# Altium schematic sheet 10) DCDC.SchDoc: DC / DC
size A3; Origin: Eagle; DocumentNumber: 10; SheetNumber: 10; SheetTotal: 10
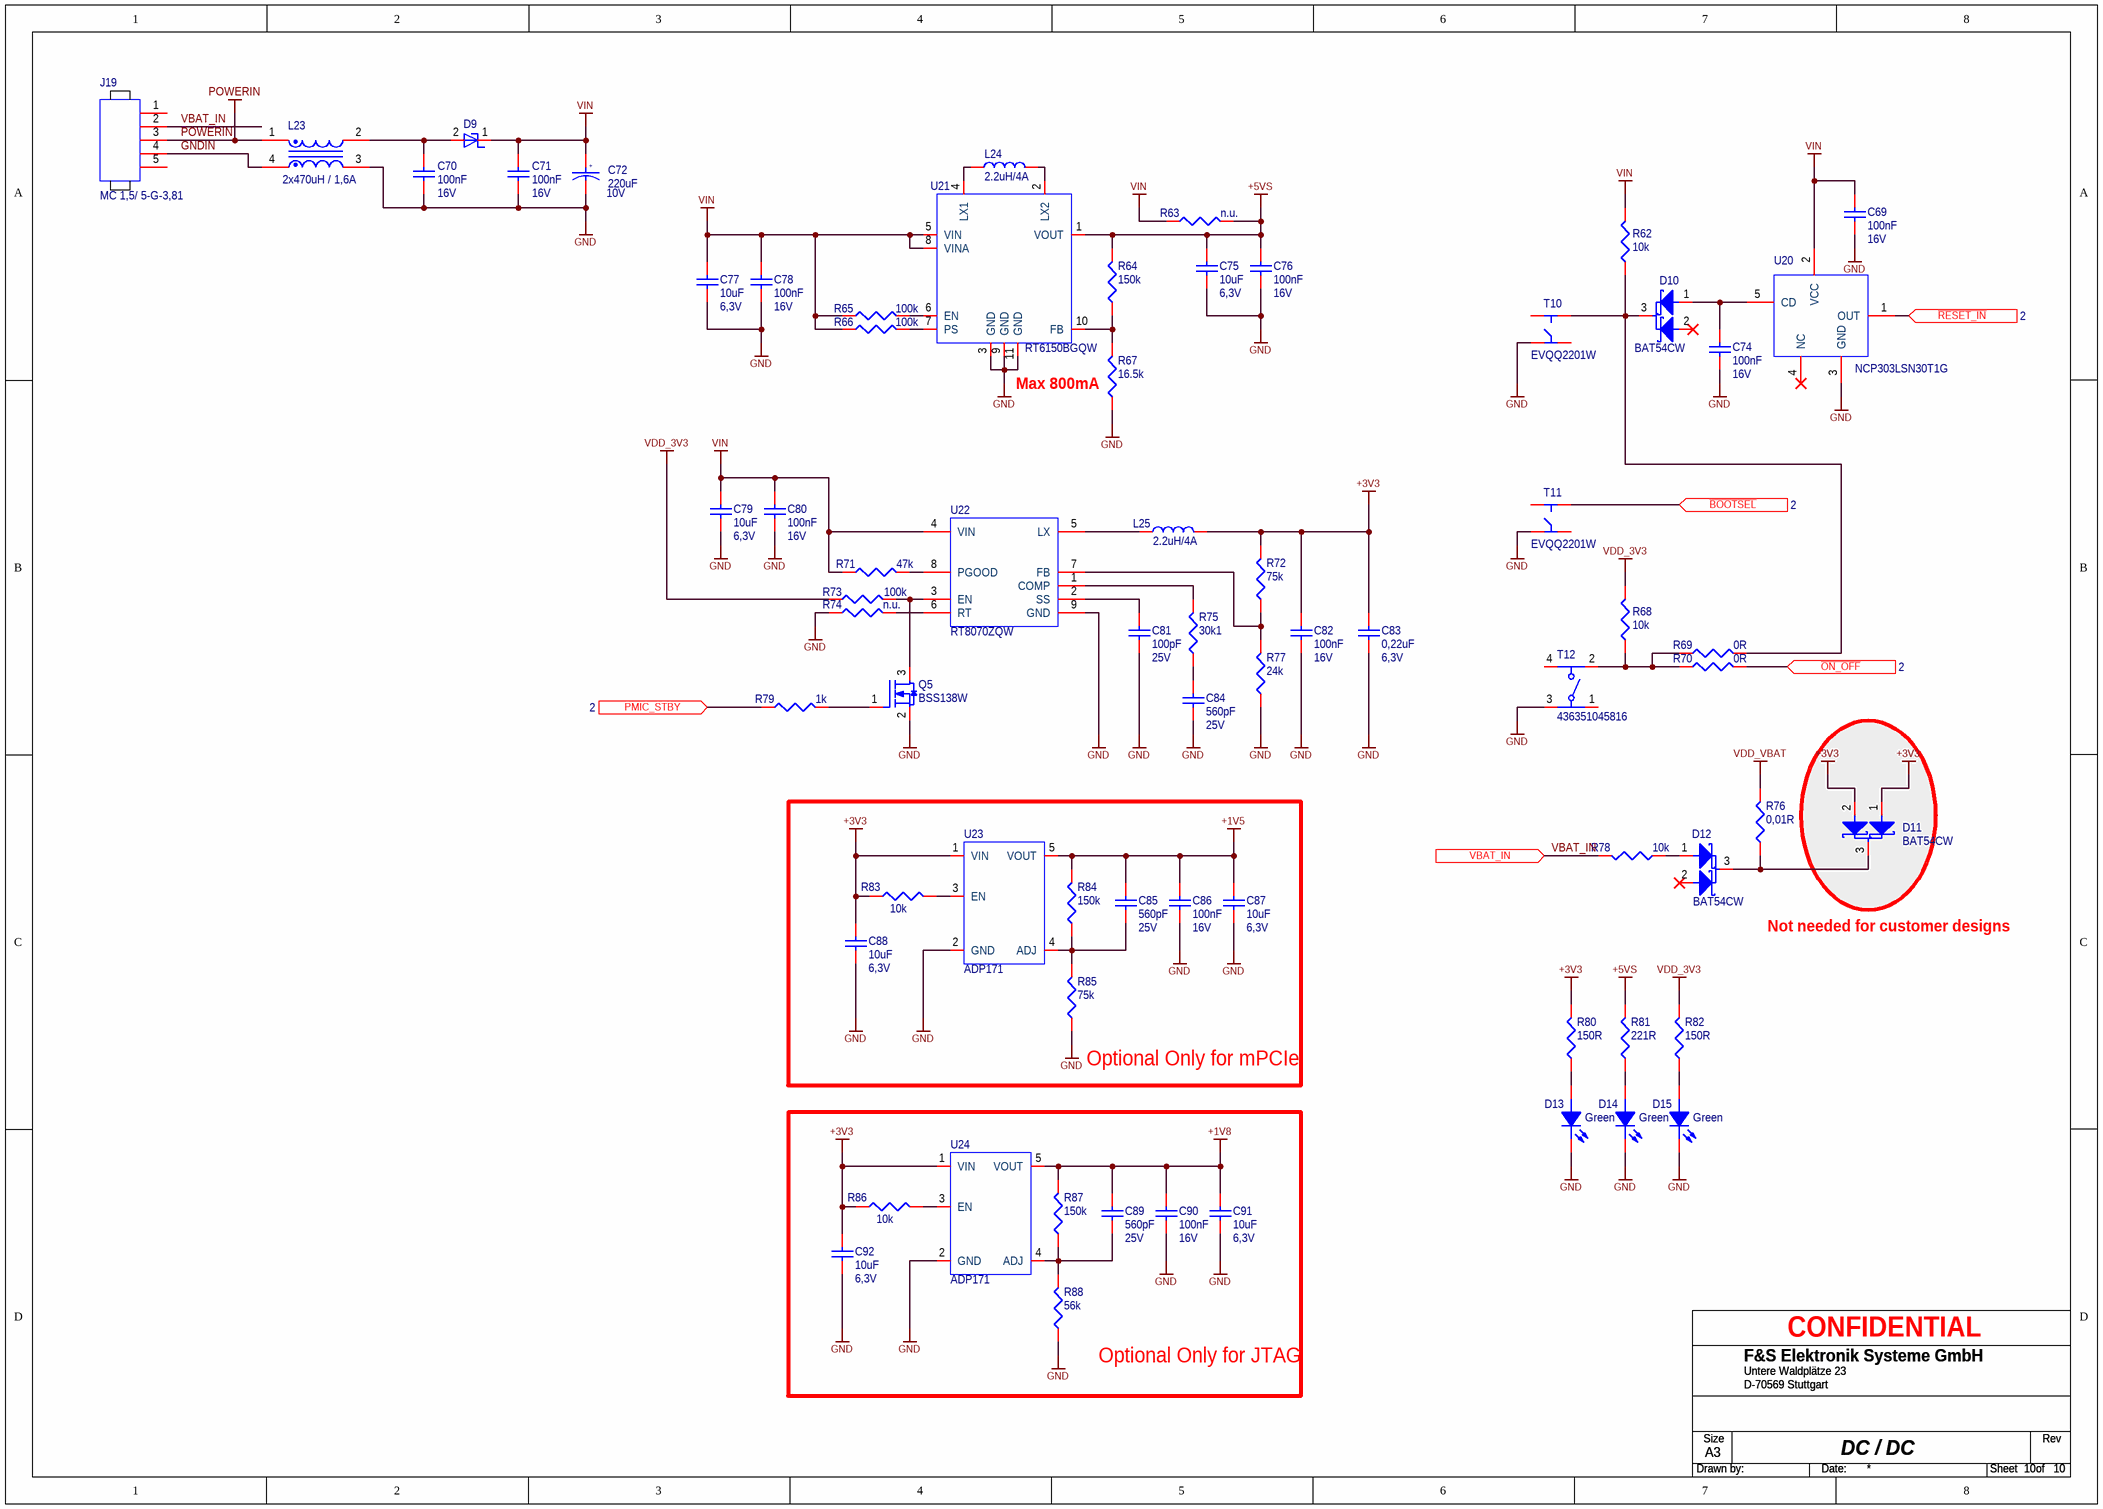
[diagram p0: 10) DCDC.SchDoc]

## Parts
C69  100nF  Voltage: 16V  [C0402]
C70  100nF  Voltage: 16V  [C0402]
C71  100nF  Voltage: 16V  [C0402]
C72  220uF  Voltage: 10V  [C_2312]
C74  100nF  Voltage: 16V  [C0402]
C75  10uF  Voltage: 6,3V  [C0603]
C76  100nF  Voltage: 16V  [C0402]
C77  10uF  Voltage: 6,3V  [C0603]
C78  100nF  Voltage: 16V  [C0402]
C79  10uF  Voltage: 6,3V  [C0603]
C80  100nF  Voltage: 16V  [C0402]
C81  100pF  Voltage: 25V  [C0402]
C82  100nF  Voltage: 16V  [C0402]
C83  0,22uF  Voltage: 6,3V  [C0805]
C84  560pF  Voltage: 25V  [C0402]
C85  560pF  Voltage: 25V  [C0402]
C86  100nF  Voltage: 16V  [C0402]
C87  10uF  Voltage: 6,3V  [C0603]
C88  10uF  Voltage: 6,3V  [C0603]
C89  560pF  Voltage: 25V  [C0402]
C90  100nF  Voltage: 16V  [C0402]
C91  10uF  Voltage: 6,3V  [C0603]
C92  10uF  Voltage: 6,3V  [C0603]
D9  SK56L  [DO-214AB]  (value not drawn)
D10  BAT54CW  [SOT323 (SC70)]
D11  BAT54CW  [SOT323 (SC70)]
D12  BAT54CW  [SOT323 (SC70)]
D13  Green  [LED0603]
D14  Green  [LED0603]
D15  Green  [LED0603]
J19  MC 1,5/ 5-G-3,81  [691322310005]
L23  2x470uH / 1,6A  [WE-SL5]
L24  2.2uH/4A  [LD-5X5M-VLC5045]
L25  2.2uH/4A  [LD-5X5M-VLC5045]
Q5  BSS138W  [SOT323 (SC70)]
R62  10k  [R0402]
R63  n.u.  [R0805]
R64  150k  [R0402]
R65  100k  [R0402]
R66  100k  [R0402]
R67  16.5k  [R0402]
R68  10k  [R0402]
R69  0R  [R0402]
R70  0R  [R0402]
R71  47k  [R0402]
R72  75k  [R0402]
R73  100k  [R0402]
R74  n.u.  [R0402]
R75  30k1  [R0402]
R76  0,01R  [R0805]
R77  24k  [R0402]
R78  10k  [R0402]
R79  1k  [R0402]
R80  150R  [R0402]
R81  221R  [R0402]
R82  150R  [R0402]
R83  10k  [R0402]
R84  150k  [R0402]
R85  75k  [R0402]
R86  10k  [R0402]
R87  150k  [R0402]
R88  56k  [R0402]
T10  EVQQ2201W  [EVQQ2 Switch]
T11  EVQQ2201W  [EVQQ2 Switch]
T12  436351045816  [436351045816]
U20  NCP303LSN30T1G  [SOT23-5]
U21  RT6150BGQW  [SON50P250X80_HS-11N]
U22  RT8070ZQW  [WDFN8_0.65P_300X80]
U23  ADP171  [SOT23-5]
U24  ADP171  [SOT23-5]

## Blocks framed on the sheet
Optional Only for mPCIe: C85-C88 R83-R85 U23
Optional Only for JTAG: C89-C92 R86-R88 U24

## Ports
PMIC_STBY (in, see 2), VBAT_IN (in), ~{BOOTSEL} (in, see 2), ~{ON_OFF} (in, see 2), ~{RESET_IN} (in, see 2)

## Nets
+1V5: C85.2 C86.2 C87.2 R84.2 U23.5(VOUT)
+1V8: C89.2 C90.2 C91.2 R87.2 U24.5(VOUT)
+3V3: C82.2 C83.2 C88.2 C92.2 D11.1(ANODE1) D11.2(ANODE2) L25.2 R72.2 R80.2 R83.1 R86.1 U23.1(VIN) U24.1(VIN)
+5VS: C75.2 C76.2 R63.2 R64.2 R81.2 U21.1(VOUT)
GND: C69.1 C70.1 C71.1 C72.2 C74.1 C75.1 C76.1 C77.1 C78.1 C79.1 C80.1 C81.1 C82.1 C83.1 C84.1 C86.1 C87.1 C88.1 C90.1 C91.1 C92.1 D13.1(CAT_GRN) D14.1(CAT_GRN) D15.1(CAT_GRN) L23.3 Q5.2 R67.1 R74.1 R77.1 R85.1 R88.1 T10.3 T11.3 T12.3 U20.3(GND) U21.3(GND) U21.9(GND) U21.11(GND) U22.9(GND) U23.2(GND) U24.2(GND)
POWERIN: J19.3 L23.1
VDD_3V3: R68.2 R73.1 R82.2
VDD_VBAT: R76.2
VIN: C69.2 C71.2 C72.1 C77.2 C78.2 C79.2 C80.2 D9.1(Anode) R62.2 R63.1 R65.1 R66.1 R71.1 U20.2(VCC) U21.5(VIN) U21.8(VINA) U22.4(VIN)
~{BOOTSEL}: T11.2 ; port ~{BOOTSEL}
GNDIN: J19.4 L23.4
~{ON_OFF}: R70.2 ; port ~{ON_OFF}
PMIC_STBY: R79.1 ; port PMIC_STBY
~{RESET_IN}: U20.1(OUT) ; port ~{RESET_IN}
VBAT_IN: J19.2 R78.2 ; port VBAT_IN
NetC70_2: C70.2 D9.2(Cathode) L23.2
NetC74_2: C74.2 D10.1(ANODE1) U20.5(CD)
NetC81_2: C81.2 U22.2(SS)
NetC84_2: C84.2 R75.1
NetC85_1: C85.1 R84.1 R85.2 U23.4(ADJ)
NetC89_1: C89.1 R87.1 R88.2 U24.4(ADJ)
NetD10_3: D10.3(CATHODE) R62.1 R69.2 T10.2
NetD11_3: D11.3(CATHODE) D12.3(CATHODE) R76.1
NetD12_1: D12.1(ANODE1) R78.1
NetD13_2: D13.2(AN_GRN) R80.1
NetD14_2: D14.2(AN_GRN) R81.1
NetD15_2: D15.2(AN_GRN) R82.1
NetL24_1: L24.1 U21.4(LX1)
NetL24_2: L24.2 U21.2(LX2)
NetL25_1: L25.1 U22.5(LX)
NetQ5_1: Q5.1 R79.2
NetQ5_3: Q5.3 R73.2 U22.3(EN)
NetR64_1: R64.1 R67.2 U21.10(FB)
NetR65_2: R65.2 U21.6(EN)
NetR66_2: R66.2 U21.7(PS)
NetR68_1: R68.1 R69.1 R70.1 T12.2
NetR71_2: R71.2 U22.8(PGOOD)
NetR72_1: R72.1 R77.2 U22.7(FB)
NetR74_2: R74.2 U22.6(RT)
NetR75_2: R75.2 U22.1(COMP)
NetR83_2: R83.2 U23.3(EN)
NetR86_2: R86.2 U24.3(EN)

Not connected (* = marked no-connect by the designer): D10 2(ANODE2)*; D12 2(ANODE2)*; J19 1 5; T10 1 4; T11 1 4; T12 1 4; U20 4(NC)*

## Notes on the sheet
- (near R67) Max 800mA
- Not needed for customer designs

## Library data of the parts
C69-C71 C74 C76 C78 C80 C82 C86 C90 = 380: 100nF  10%  16V  X7R  0402; FS-EDV-Nummer: B.CKV.42; Class: Capacitor Ceramic; Tolerance: 10; ID: 380
C72 = 718: 220uF  20%  10V  2312  Typ: C; FS-EDV-Nummer: B.CTA.16; Class: Capacitor Tantal; Tolerance: 20; ID: 718
C75 C77 C79 C87 C88 C91 C92 = 406: 10uF  20%  6,3V  X5R  0603; FS-EDV-Nummer: B.CKV.46; Class: Capacitor Ceramic; Tolerance: 20; ID: 406
C81 = 387: 100pF  5%  25V  C0G/NP0  0402; FS-EDV-Nummer: B.CKV.68; Class: Capacitor Ceramic; Tolerance: 5; ID: 387
C83 = 439: 0,22uF  10%  6,3V  X7R  0805; FS-EDV-Nummer: B.CKV.62; Class: Capacitor Ceramic; Tolerance: 10; ID: 439
C84 C85 C89 = 388: 560pF  5%  25V  X7R  0402; FS-EDV-Nummer: B.CKV.71; Class: Capacitor Ceramic; Tolerance: 5; ID: 388
D9 = 2696: SK56L-TP  60V  5A  Common Anode  DO-214AB; ID: 2696; Class: DIOD; FS-EDV-Nummer: B.DSCHOT.4
D10-D12 = 2695: BAT54CW  30V  200mA  Dual Common Cathode SOT-323; FS-EDV-Nummer: B.DSCHOT.5; Class: DIOD; ID: 2695
D13-D15 = 2744: LED  Green  View 120°  0603; Part Number: APT1608CGCK; ID: 2744; FS-EDV-Nummer: B.DLED.11
J19 = 2729: Stiftl. 5 pol.1 reih. R3,81  liegend; ID: 2729; Class: Connector; FS-EDV-Nummer: B.MST.1R5PS.5
L23 = 2697: 2x470uH 1,6A SMD; ID: 2697; FS-EDV-Nummer: B.L.56; Power: 1,6A
L24 L25 = 2741: ID: 2741; FS-EDV-Nummer: B.L.42; Power: 4A
Q5 = 2689: BSS138W SOT323(SC-70) N-Kanal; FS-EDV-Nummer: B.TPMFN.10; Class: MOSFET; ID: 2689
R62 R68 R78 R83 R86 = 170: 10k 1/16W 1% SMD 0402; FS-EDV-Nummer: B.R10K.3; Tolerance: 1; ID: 170
R63 = B.R000.2.S: 0R00 0,125W max 5% SMD 0805; Power: 0,125W; Tolerance: 5; ID: 6
R64 R84 R87 = 204: 150k 1/16W 1% SMD 0402; FS-EDV-Nummer: B.R150K.2; Tolerance: 1; ID: 204
R65 R66 R73 = 177: 100k 1/16W 1% SMD 0402; FS-EDV-Nummer: B.R100K.3; Tolerance: 1; ID: 177
R67 = 303: 16.5k 1/16W 1% SMD 0402; FS-EDV-Nummer: B.R16K5.1; Tolerance: 1; ID: 303
R69 R70 = 173: 0R 1/16W max 5% SMD 0402; FS-EDV-Nummer: B.R0R0.1; Tolerance: 5; ID: 173
R71 = 186: 47k 1/16W 1% SMD 0402; FS-EDV-Nummer: B.R47K0.1; Tolerance: 1; ID: 186
R72 R85 = 191: 75k 1/16W 1% SMD 0402; FS-EDV-Nummer: B.R75K0.1; Tolerance: 1; ID: 191
R74 = Resistor
R75 = 197: 30k1 1/16W 1% SMD 0402; FS-EDV-Nummer: B.R30K1.1; Tolerance: 1; ID: 197
R76 = 187: 0,01R 1/4W max 5% SMD 0805; FS-EDV-Nummer: B.R0R01.1; Tolerance: 5; ID: 187
R77 = 254: 24k 1/16W 1% SMD 0402; FS-EDV-Nummer: B.R24k0.1; Tolerance: 1; ID: 254
R79 = 166: 1k 1/16W 1% SMD 0402; FS-EDV-Nummer: B.R1K00.1; Tolerance: 1; ID: 166
R80 R82 = 172: 150R 1/16W 1% SMD 0402; FS-EDV-Nummer: B.R150R.1; Tolerance: 1; ID: 172
R81 = 174: 221R 1/16W 1% SMD 0402; FS-EDV-Nummer: B.R221R.1; Tolerance: 1; ID: 174
R88 = 326: 56k 1/16W 1% SMD 0402; FS-EDV-Nummer: B.R56K.2; Tolerance: 1; ID: 326
T10 T11 = 2735: Miniatur-Tastschalter Serie EVQ SMD; FS-EDV-Nummer: B.MSW.4; Voltage: 15V; Class: Switch; Power: 20 mA; ID: 2735
T12 = 2736: Tact Switch side push; FS-EDV-Nummer: B.MSW.5; Voltage: 12V; ID: 2736
U20 = 1726: NCP303LSN30T1G  3V  TSOP-5; FS-EDV-Nummer: B.ICANA.45; Class: IC; ID: 1726
U21 = 2789: RT6150B DFN10 2.5x2.5mm; ID: 2789; Class: IC; FS-EDV-Nummer: B.ICANA.114
U22 = 1736: RT8070ZQW ADJ 4A Sync WDFN-8 (-40°C bis 85°C); FS-EDV-Nummer: B.ICANA.54; Voltage: max. 5,5V; Class: IC; ID: 1736
U23 U24 = 1740: ADP171AUJZ-R7 ADJ 300mA VIN max. 3,6V TSOT-5 SMD; FS-EDV-Nummer: B.ICANA.58; Voltage: 3,6V; Class: IC; ID: 1740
